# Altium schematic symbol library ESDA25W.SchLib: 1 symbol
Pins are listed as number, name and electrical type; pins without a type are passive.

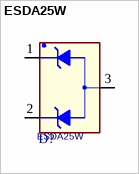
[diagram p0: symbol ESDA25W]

## ESDA25W
designator D?
footprint ST_SOT323-3L
pins: 1, 2, 3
